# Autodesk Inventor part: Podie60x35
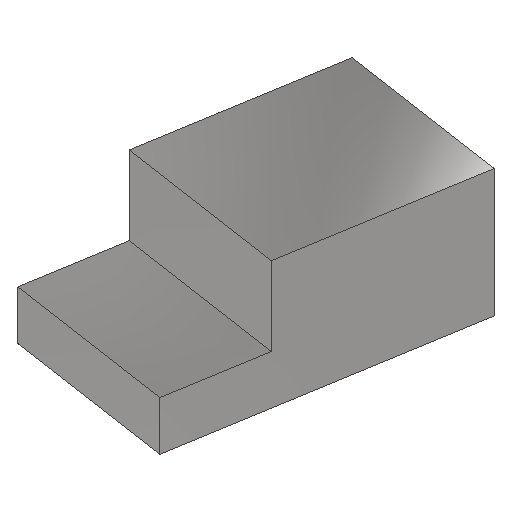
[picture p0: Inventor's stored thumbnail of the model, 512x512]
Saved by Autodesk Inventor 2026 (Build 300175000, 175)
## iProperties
Created: 2004-09
Part Number: Podie60x35
Document SubType Name: Modeling
Designer: Lars Bertram Pedersen
Manufacturer: Standard
Standards Organization: Custom
Material: Steel, Mild
Density: 7.85 g/cm^3
Appearance: Semi-Polished
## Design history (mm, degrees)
sketch "Sketch1"
  geometry: L1 (-60, 0)-(0, 0); L2 (0, 0)-(0, 10); L3 (0, 10)-(-20, 10); L4 (-20, 10)-(-20, 26); L5 (-20, 26)-(-60, 26); L6 (-60, 26)-(-60, 0); 1 further point
  constraints: 12 end point, 3 perpendicular, 2 parallel, 1 coincident, 1 horizontal
  dimensions: "d0" = 60 distance of L1.start L1.end; "d1" = 10 distance of L1.end L2.end; "d2" = 16 distance of L3.end L4.end; "d3" = 40 distance of L4.end L5.end
extrude "Extrusion1" new body sketch "Sketch1" distance "d4" = 35; taper "d5" = 0 deg
body "Solid1"
